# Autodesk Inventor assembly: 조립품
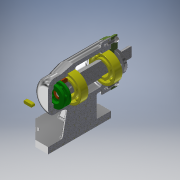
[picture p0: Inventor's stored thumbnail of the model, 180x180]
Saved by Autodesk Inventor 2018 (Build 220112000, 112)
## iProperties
Created: 2021-01
Part Number: 조립품
Material: 일반
Document SubType Name: Assembly
Designer: home
Author: home
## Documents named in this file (10)
- C:\Users\home\Desktop\710106V1035\조립품.iam
- C:\Users\home\Desktop\710106V1035\본체.ipt
- C:\Users\home\Desktop\710106V1035\베어링 6004.ipt
- C:\Users\home\Desktop\710106V1035\커버.ipt
- C:\Users\home\Desktop\710106V1035\볼트 M4.ipt
- C:\Users\home\Desktop\710106V1035\오일 실.ipt
- C:\Users\home\Desktop\710106V1035\어댑터슬리브.ipt
- C:\Users\home\Desktop\710106V1035\베어링 51202.ipt
- C:\Users\home\Desktop\710106V1035\축.ipt
- C:\Users\home\Desktop\710106V1035\키 5 x 5 x 14.ipt
